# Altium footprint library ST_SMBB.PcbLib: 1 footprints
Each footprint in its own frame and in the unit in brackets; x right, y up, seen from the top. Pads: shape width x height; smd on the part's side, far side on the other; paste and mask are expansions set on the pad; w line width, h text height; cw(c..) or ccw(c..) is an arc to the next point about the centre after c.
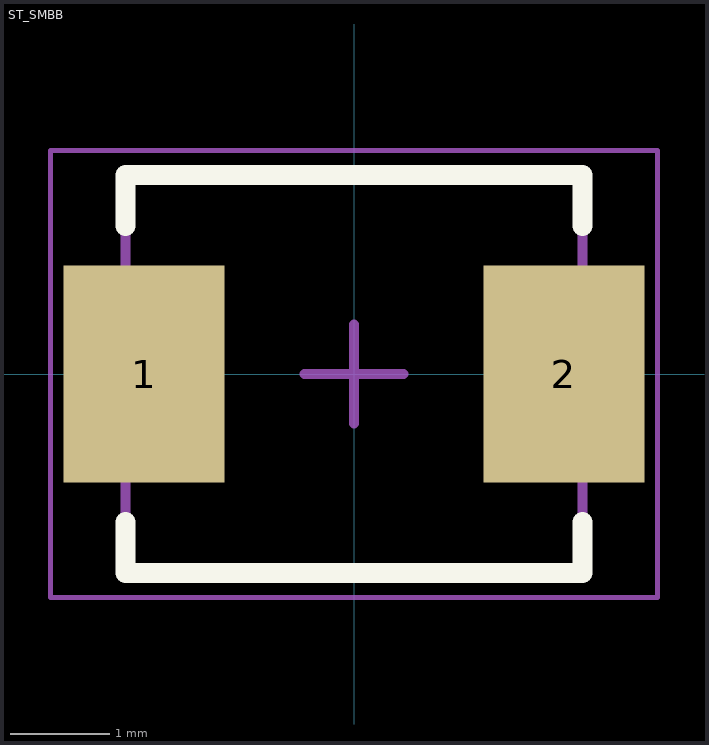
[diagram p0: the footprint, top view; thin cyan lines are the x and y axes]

## ST_SMBB [mm] "SMB Bidir TVS"
height 2.65
pads (2):
  rect 1.62x2.18 smd: 1(-2.11,0) 2(2.11,0)
Top Overlay:
  lines w0.2: -2.3,-1.49 -2.3,-2 2.3,-2 2.3,-1.49 ; -2.3,1.49 -2.3,2 2.3,2 2.3,1.49
Mechanical 13:
  lines w0.1: -2.3,-1.975 2.3,-1.975 2.3,1.975 -2.3,1.975 -2.3,-1.975
Mechanical 15:
  lines w0.05: -3.05,-2.25 3.05,-2.25 3.05,2.25 -3.05,2.25 -3.05,-2.25
  lines w0.1: -0.5,0 0.5,0 ; 0,-0.5 0,0.5
3D body "ST_SMBB.step": height 2.65, standoff 0, extent -2.52,-1.975 2.52,1.975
